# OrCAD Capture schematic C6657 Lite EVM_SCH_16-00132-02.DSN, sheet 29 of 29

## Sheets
29 PAGE22 : FPGA-POWER,RESET,McBSP: size C; title: FPGA-POWER,RESET,McBSP
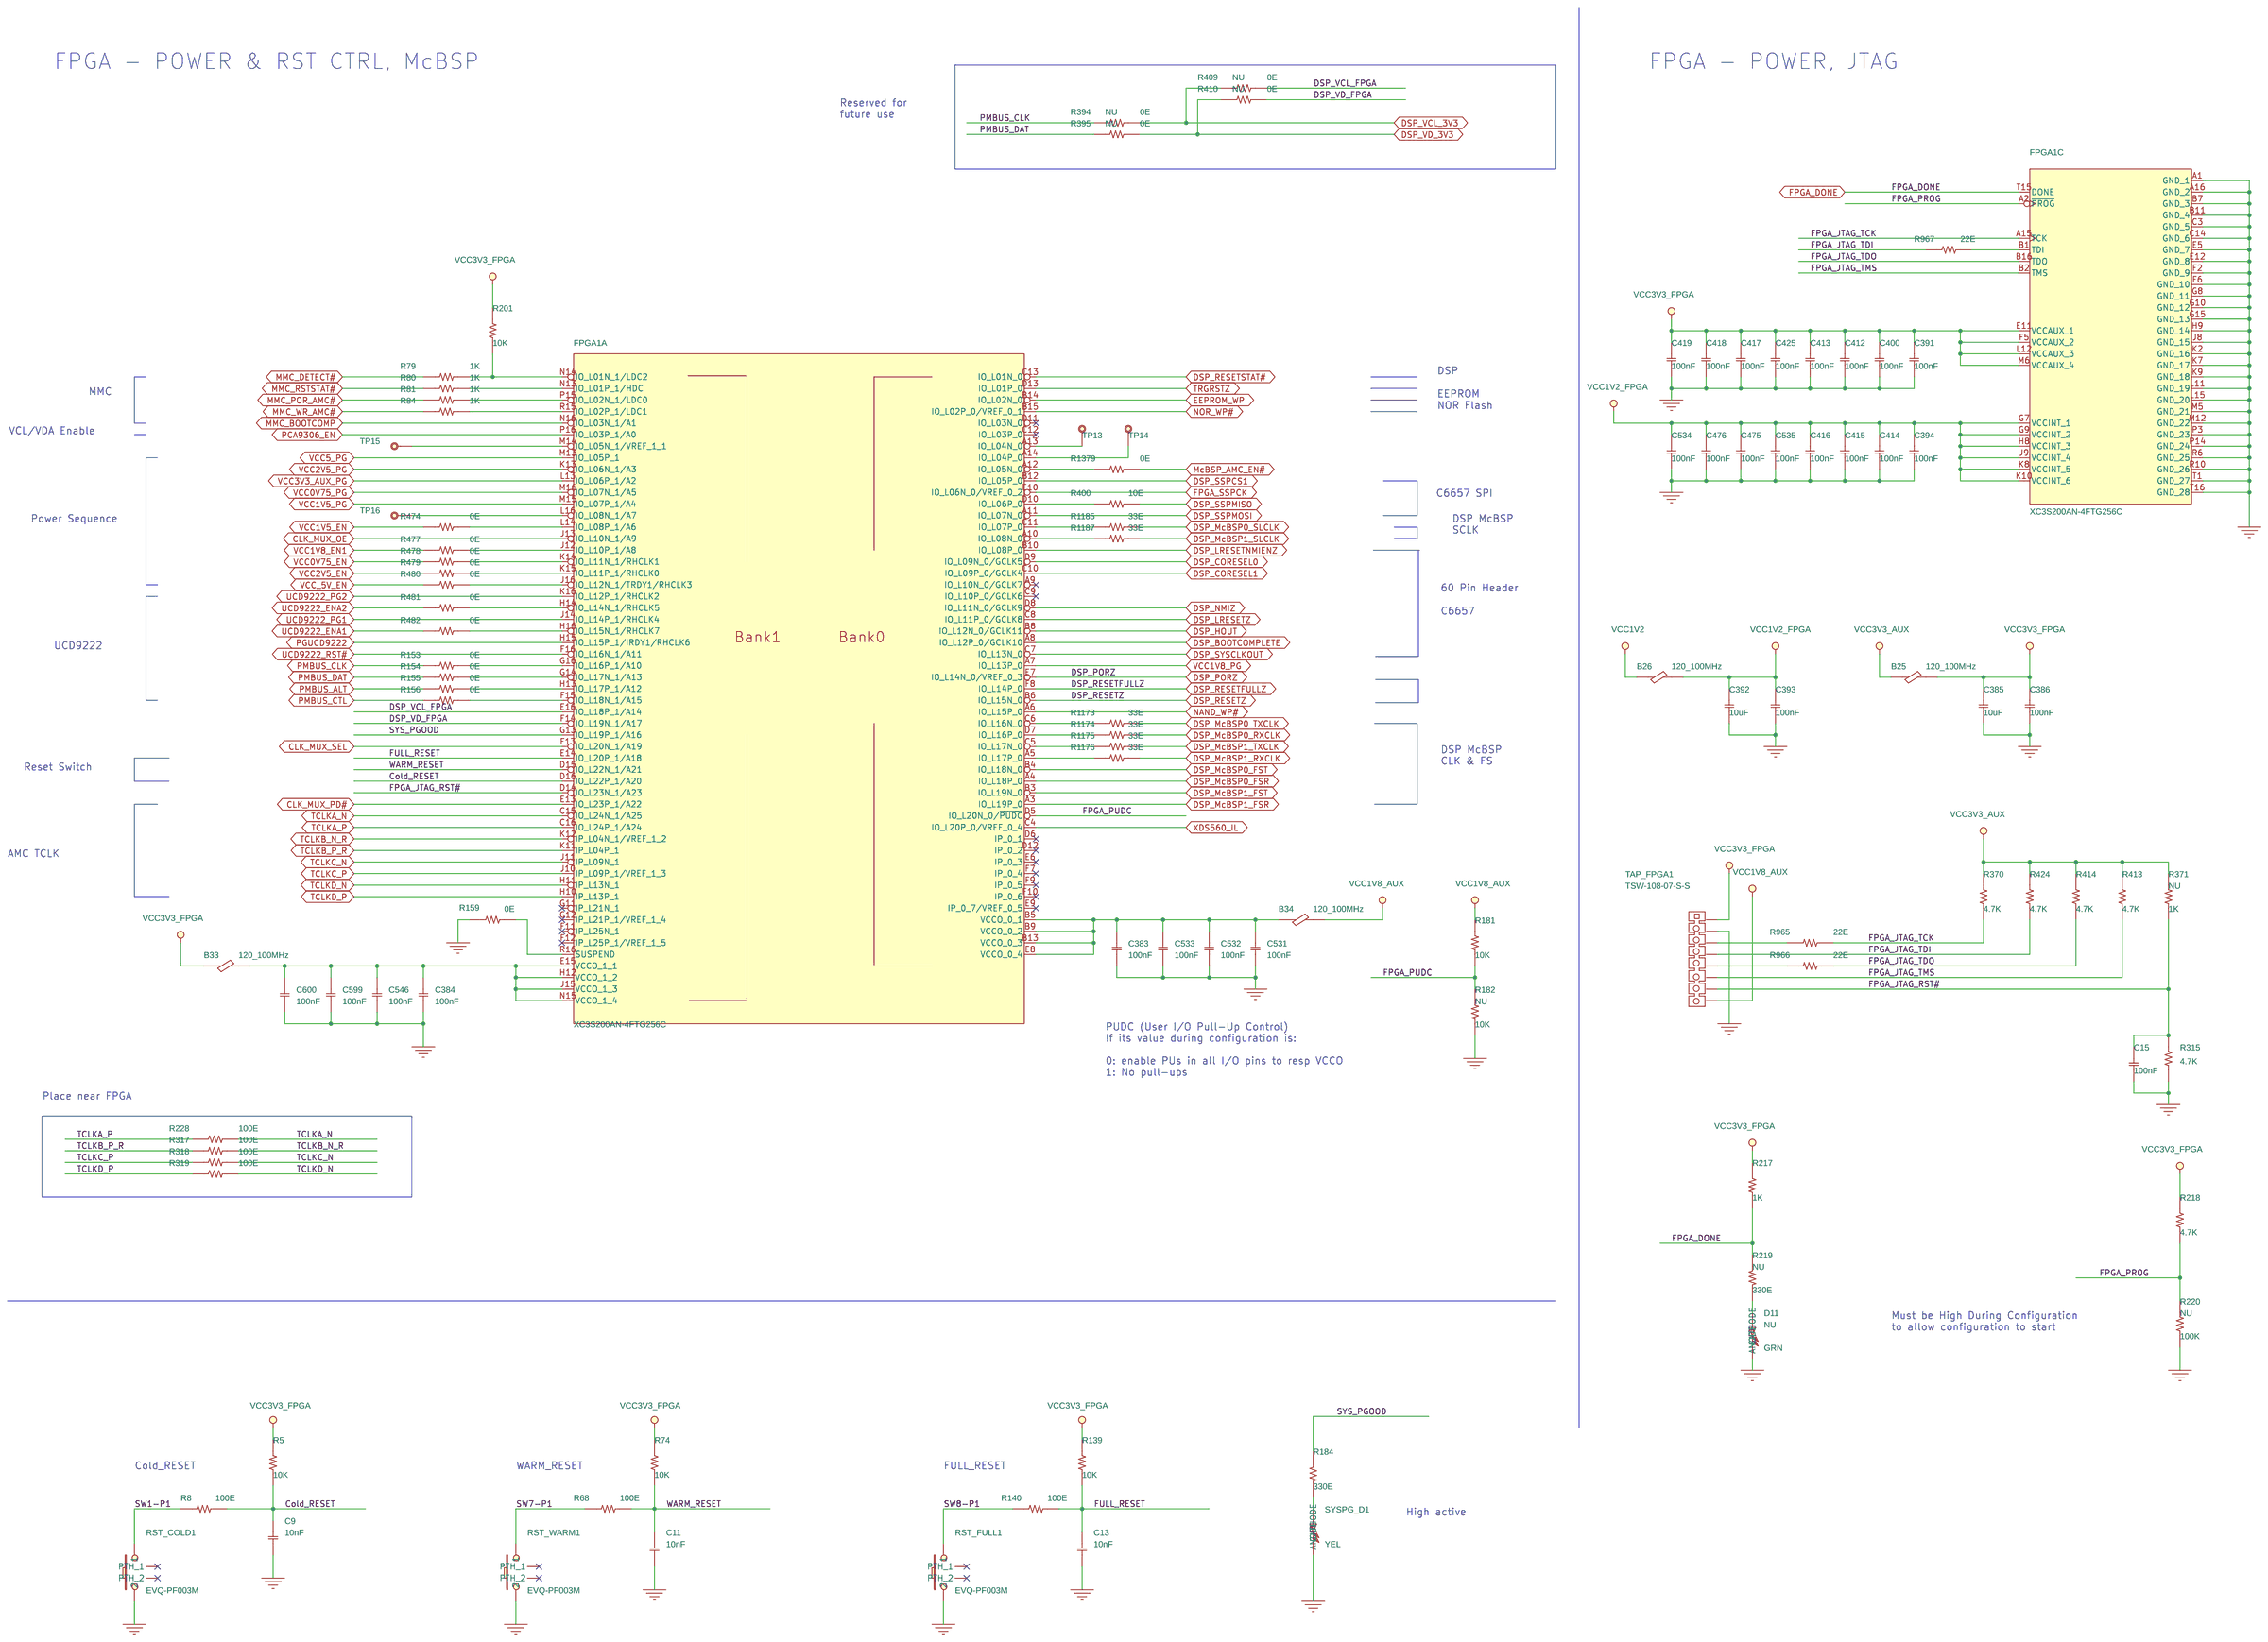
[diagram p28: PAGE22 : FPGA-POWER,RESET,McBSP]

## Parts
sheet PAGE22 : FPGA-POWER,RESET,McBSP
B25  120_100MHz  [L0603]
B26  120_100MHz  [L0603]
B33  120_100MHz  [L0603]
B34  120_100MHz  [L0603]
C9  10nF  [C0402]
C11  10nF  [C0402]
C13  10nF  [C0402]
C15  100nF  [C0402]
C383  100nF  [C0402]
C384  100nF  [C0402]
C385  10uF  [C0603]
C386  100nF  [C0402]
C391  100nF  [C0402]
C392  10uF  [C0603]
C393  100nF  [C0402]
C394  100nF  [C0402]
C400  100nF  [C0402]
C412  100nF  [C0402]
C413  100nF  [C0402]
C414  100nF  [C0402]
C415  100nF  [C0402]
C416  100nF  [C0402]
C417  100nF  [C0402]
C418  100nF  [C0402]
C419  100nF  [C0402]
C425  100nF  [C0402]
C475  100nF  [C0402]
C476  100nF  [C0402]
C531  100nF  [C0402]
C532  100nF  [C0402]
C533  100nF  [C0402]
C534  100nF  [C0402]
C535  100nF  [C0402]
C546  100nF  [C0402]
C599  100nF  [C0402]
C600  100nF  [C0402]
D11  GRN  [LED_0603]
R5  10K  [R0402]
R8  100E  [R0402]
R68  100E  [R0402]
R74  10K  [R0402]
R79  1K  [R0402]
R80  1K  [R0402]
R81  1K  [R0402]
R84  1K  [R0402]
R139  10K  [R0402]
R140  100E  [R0402]
R153  0E  [R0402]
R154  0E  [R0402]
R155  0E  [R0402]
R156  0E  [R0402]
R159  0E  [R0402]
R181  10K  [R0402]
R182  10K  [R0402]
R184  330E  [R0402]
R201  10K  [R0402]
R217  1K  [R0402]
R218  4.7K  [R0402]
R219  330E  [R0402]
R220  100K  [R0402]
R228  100E  [R0402]
R315  4.7K  [R0402]
R317  100E  [R0402]
R318  100E  [R0402]
R319  100E  [R0402]
R370  4.7K  [R0402]
R371  1K  [R0402]
R394  0E  [R0402]
R395  0E  [R0402]
R400  10E  [R0402]
R409  0E  [R0402]
R410  0E  [R0402]
R413  4.7K  [R0402]
R414  4.7K  [R0402]
R424  4.7K  [R0402]
R474  0E  [R0402]
R477  0E  [R0402]
R478  0E  [R0402]
R479  0E  [R0402]
R480  0E  [R0402]
R481  0E  [R0402]
R482  0E  [R0402]
R965  22E  [R0402]
R966  22E  [R0402]
R967  22E  [R0402]
R1173  33E  [R0402]
R1174  33E  [R0402]
R1175  33E  [R0402]
R1176  33E  [R0402]
R1185  33E  [R0402]
R1187  33E  [R0402]
R1379  0E  [R0402]
RST_COLD1  EVQ-PF003M  [SW_EVQ-PF003M]
RST_FULL1  EVQ-PF003M  [SW_EVQ-PF003M]
RST_WARM1  EVQ-PF003M  [SW_EVQ-PF003M]
SYSPG_D1  YEL  [LED_LTST-C171]
TAP_FPGA1  TSW-108-07-S-S  [HD_8x1P_100_D]
TP13  Test Point  [TP-S40]
TP14  Test Point  [TP-S40]
TP15  Test Point  [TP-S40]
TP16  Test Point  [TP-S40]
sheet PAGE23 : FPGA-BM & SMART REF
FPGA1  XC3S200AN-4FTG256C  [BGA_256P_39_669x669_H61]  (sections A,B,C)

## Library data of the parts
B25 B26 B33 B34 = 1212_BEAD_0: FERRITE CHIP 120 OHM 2000MA 0603; Manufacture Part Number: BLM18PG121SN1; Mfg: Murata; Mfg Part#: BLM18PG121SN1D; Oper. Temp. Range: -55C to 85C; Package: 0603; ProcessType: SMT; RoHS: Yes; Tolerance: 25%; Vendor: DigiKey; Vendor Part#: 490-1037-1-ND; eI Part#: 04_00023_01
C9 C11 C13 = 11_C_0: CAP 10nF 16V CERAMIC 0402 SMD; Alt Mfg: Murata; Alt Mfg Part#: GRM155R71C103KA01D; Manufacture Part Number: C1005X7R1C103K||2238 787 15636||CC0402KRX7R7BB103; Mfg: Panasonic - ECG; Mfg Part#: ECJ-0EB1C103K; Oper. Temp. Range: -55C to 125C; Package: 0402; ProcessType: SMT; RoHS: Yes; Tolerance: 10%; Vendor: DigiKey; Vendor Part#: PCC103BQCT-ND; eI Part#: 03_00025_01
C15 C383 C384 C386 C391 C393 C394 C400 C412-C419 C425 C475 C476 C531-C535 C546 C599 C600 = 11_C_0: CAP CER 0.1UF 10V 10% X5R 0402; Alt Mfg: Murata; Alt Mfg Part#: GRM155R61A104KA01D; Manufacture Part Number: 2238 787 15649||CC0402KRX7R7BB104; Mfg: Yageo; Mfg Part#: CC0402KRX5R6BB104; Oper. Temp. Range: -55C to 85C; Package: 0402; ProcessType: SMT; RoHS: Yes; Tolerance: 10%; Vendor: DigiKey; Vendor Part#: 311-1336-1-ND; eI Part#: 03_00021_02
C385 C392 = 11_C_0: CAP CER 10UF 6.3V 20% X5R 0603; Manufacture Part Number: C1608X5R0J106MT||2255 206 13776||CC0603MRX5R5BB106; Mfg: Murata; Mfg Part#: GRM188R60J106ME47D; Oper. Temp. Range: -55C to 85C; Package: 0603; ProcessType: SMT; RoHS: Yes; Tolerance: 20%; Vendor: DigiKey; Vendor Part#: 490-3896-1-ND; eI Part#: 03_00058_03
D11 = 130_LED_LED-0603_G_0: LED 565NM GRN DIFF 0603 SMD; Manufacture Part Number: KP-1608SGD; Mfg: Lumex Opto/Components Inc; Mfg Part#: SML-LX0603GW-TR; Mounting Status: NU; Package: 0603; ProcessType: SMT; RoHS: Yes; Vendor: DigiKey; Vendor Part#: 67-1549-1-ND; eI Part#: 06_00007_01
R5 R74 R139 R181 R201 = 10_R_0: RES 10.0K OHM 1/10W 1% 0402 SMD; Alt Mfg: Yageo; Alt Mfg Part#: RC0402FR-0710KL; Manufacture Part Number: 0402WGF1002TCE||RM04FTN1002; Mfg: Panasonic - ECG; Mfg Part#: ERJ-2RKF1002X; Oper. Temp. Range: -55C ~ 125C; Package: 0402; ProcessType: SMT; Remark: Alt part is 1/16W; RoHS: Yes; Tolerance: 1%; Vendor: DigiKey; Vendor Part#: P10.0KLCT-ND; eI Part#: 02_00027_01
R8 R68 R140 R228 R317-R319 = 10_R_0: RES 100 OHM 1/10W 1% 0402 SMD; Manufacture Part Number: 0402WGF1000TCE||232270671001L||RM04FTN1000; Mfg: Panasonic - ECG; Mfg Part#: ERJ-2RKF1000X; Oper. Temp. Range: -55C to 125C; Package: 0402; ProcessType: SMT; RoHS: Yes; Tolerance: 1%; Vendor: DigiKey; Vendor Part#: P100LCT-ND; eI Part#: 02_00043_02
R79-R81 R84 R217 = 10_R_0: RES 1.00K OHM 1/10W 1% 0402 SMD; Alt Mfg: Yageo; Alt Mfg Part#: RC0402FR-071KL; MOUNTED: <MOUNTED>; Manufacture Part Number: 0402WGF1001TCE||RM04FTN1001; Mfg: Panasonic - ECG; Mfg Part#: ERJ-2RKF1001X; Oper. Temp. Range: -55C to 125C; Package: 0402; ProcessType: SMT; RoHS: Yes; Tolerance: 1%; Vendor: DigiKey; Vendor Part#: P1.00KLCT-ND; eI Part#: 02_00045_01
R153-R156 R159 R474 R477-R482 R1379 = 10_R_0: RES ZERO OHM 1/10W 5% 0402 SMD; Alt Mfg: Yageo; Alt Mfg Part#: RC0402JR-070RL; Mfg: Panasonic - ECG; Mfg Part#: ERJ-2GE0R00X; Oper. Temp. Range: -55C to 125C; Package: 0402; ProcessType: SMT; Remark: Alt part is 1/16W; RoHS: Yes; Tolerance: 5%; Vendor: DigiKey; Vendor Part#: P0.0JCT-ND; eI Part#: 02_00019_01
R182 = 10_R_0: RES 10.0K OHM 1/10W 1% 0402 SMD; Alt Mfg: Yageo; Alt Mfg Part#: RC0402FR-0710KL; Manufacture Part Number: 0402WGF1002TCE||RM04FTN1002; Mfg: Panasonic - ECG; Mfg Part#: ERJ-2RKF1002X; Mounting Status: NU; Mounting_Status: NU; Oper. Temp. Range: -55C ~ 125C; Package: 0402; ProcessType: SMT; Remark: Alt part is 1/16W; RoHS: Yes; Tolerance: 1%; Vendor: DigiKey; Vendor Part#: P10.0KLCT-ND; eI Part#: 02_00027_01
R184 = 10_R_0: RES 330 OHM 1/10W 5% 0402 SMD; Alt Mfg: Yageo; Alt Mfg Part#: RC0402JR-07330RL; Manufacture Part Number: 0402WGJ0331TCE||RM04JTN331; Mfg: Panasonic - ECG; Mfg Part#: ERJ-2GEJ331X; Package: 0402; ProcessType: SMT; Remark: Alt part is 1/16W; RoHS: Yes; Tolerance: 5%; Vendor: DigiKey; Vendor Part#: P330JCT-ND; eI Part#: 02_00032_01
R218 = 10_R_0: RES 4.7K OHM 1/10W 5% 0402 SMD; Alt Mfg: Yageo; Alt Mfg Part#: RC0402JR-074K7L; Manufacture Part Number: 0402WGJ0472TCE||RC0402JR-074K7L||RM04JTN472; Mfg: Panasonic - ECG; Mfg Part#: ERJ-2GEJ472X; Oper. Temp. Range: -55C to 125C; Package: 0402; ProcessType: SMT; Remark: Alt part is 1/16W; RoHS: Yes; Tolerance: 5%; Vendor: DigiKey; Vendor Part#: P4.7KJCT-ND; eI Part#: 02_00023_01
R219 = 10_R_0: RES 330 OHM 1/10W 5% 0402 SMD; Alt Mfg: Yageo; Alt Mfg Part#: RC0402JR-07330RL; Manufacture Part Number: 0402WGJ0331TCE||RM04JTN331; Mfg: Panasonic - ECG; Mfg Part#: ERJ-2GEJ331X; Mounting Status: NU; Mounting_Status: NU; Package: 0402; ProcessType: SMT; Remark: Alt part is 1/16W; RoHS: Yes; Tolerance: 5%; Vendor: DigiKey; Vendor Part#: P330JCT-ND; eI Part#: 02_00032_01
R220 = 10_R_0: RES 100K OHM 1/10W 1% 0402 SMD; Alt Mfg: Yageo; Alt Mfg Part#: RC0402FR-07100KL; Manufacture Part Number: 0402WGF1003TCE||RM04FTN1003; Mfg: Panasonic - ECG; Mfg Part#: ERJ-2RKF1003X; Mounting Status: NU; Mounting_Status: NU; Oper. Temp. Range: ±100ppm/°C; Package: 0402; ProcessType: SMT; RoHS: Yes; Tolerance: 1%; Vendor: DigiKey; Vendor Part#: P100KLCT-ND; eI Part#: 02_00262_01
R315 R370 R413 R414 R424 = 10_R_0: RES 4.7K OHM 1/10W 5% 0402 SMD; Alt Mfg: Yageo; Alt Mfg Part#: RC0402JR-074K7L; MOUNTED: <MOUNTED>; Manufacture Part Number: 0402WGJ0472TCE||RC0402JR-074K7L||RM04JTN472; Mfg: Panasonic - ECG; Mfg Part#: ERJ-2GEJ472X; Oper. Temp. Range: -55C to 125C; Package: 0402; ProcessType: SMT; Remark: Alt part is 1/16W; RoHS: Yes; Tolerance: 5%; Vendor: DigiKey; Vendor Part#: P4.7KJCT-ND; eI Part#: 02_00023_01
R371 = 10_R_0: RES 1.00K OHM 1/10W 1% 0402 SMD; Alt Mfg: Yageo; Alt Mfg Part#: RC0402FR-071KL; Manufacture Part Number: 0402WGF1001TCE||RM04FTN1001; Mfg: Panasonic - ECG; Mfg Part#: ERJ-2RKF1001X; Mounting Status: NU; Mounting_Status: NU; Oper. Temp. Range: -55C to 125C; Package: 0402; ProcessType: SMT; RoHS: Yes; Tolerance: 1%; Vendor: DigiKey; Vendor Part#: P1.00KLCT-ND; eI Part#: 02_00045_01
R394 R395 R409 R410 = 10_R_0: RES ZERO OHM 1/10W 5% 0402 SMD; Alt Mfg: Yageo; Alt Mfg Part#: RC0402JR-070RL; Mfg: Panasonic - ECG; Mfg Part#: ERJ-2GE0R00X; Mounting Status: NU; Mounting_Status: NU; Oper. Temp. Range: -55C to 125C; Package: 0402; ProcessType: SMT; Remark: Alt part is 1/16W; RoHS: Yes; Tolerance: 5%; Vendor: DigiKey; Vendor Part#: P0.0JCT-ND; eI Part#: 02_00019_01
R400 = 10_R_0: RES 10.0 OHM 1/10W 1% 0402 SMD; Manufacture Part Number: 0402WGJ0100TCE||RC0402JR-0710RL||RM04JTN100; Mfg: Panasonic - ECG; Mfg Part#: ERJ-2RKF10R0X; Oper. Temp. Range: -55C to 125C; Package: 0402; ProcessType: SMT; RoHS: Yes; Tolerance: 1%; Vendor: DigiKey; Vendor Part#: P10.0LCT-ND; eI Part#: 02_00060_01
R965-R967 = 10_R_0: RES 22 OHM 1/10W 5% 0402 SMD; Mfg: Panasonic - ECG; Mfg Part#: ERJ-2GEJ220X; Oper. Temp. Range: -55C to 125C; Package: 0402; ProcessType: SMT; Remark: Alt part is 1/16W; RoHS: Yes; Tolerance: 5%; Vendor: DigiKey; Vendor Part#: P22JCT-ND; eI Part#: 02_00233_01
R1173-R1176 R1185 R1187 = 10_R_0: RES 33.0 OHM 1/10W 1% 0402 SMD; Alt Mfg: Yageo; Alt Mfg Part#: RC0402FR-0733RL; Manufacture Part Number: 0402WGJ0330TCE||232270570339L||RC0402JR-0733RL||RM04JTN330; Mfg: Panasonic - ECG; Mfg Part#: ERJ-2RKF33R0X; Oper. Temp. Range: -55C to 125C; Package: 0402; ProcessType: SMT; Remark: Alt part is 1/16W; RoHS: Yes; Tolerance: 1%; Vendor: DigiKey; Vendor Part#: P33.0LCT-ND; eI Part#: 02_00018_05
RST_COLD1 RST_FULL1 RST_WARM1 = 160_SW-HDK632: SWITCH TACTILE SPST-NO 0.02A 15V; Manufacture Part Number: HDK632AR-ST; Mfg: Panasonic - ECG; Package: SW2PDIP; ProcessType: DIP; RoHS: Yes; Vendor: DigiKey; Vendor Part#: P10877S-ND; eI Part#: 11_00020_01
SYSPG_D1 = 130_LED_2P_B_0: LED AMBER YEL CLR THIN 0805 SMD; Alt Mfg: Lite-On Inc; Alt Mfg Part#: LTST-C170KSKT; Mfg: Lite-On Inc; Mfg Part#: LTST-C171KYKT; Package: 0805; ProcessType: SMT; RoHS: Yes; Vendor: DigiKey; Vendor Part#: 160-1429-1-ND; eI Part#: 06_00087_01
TAP_FPGA1 = 1653_JH8X1V_0: CONN HEADER 8POS .100" SGL GOLD; Manufacture Part Number: YP91-01104-08B1||21N12564-08S10B-01G-6/3; Mfg: Samtec; Package: PH8x1P-2.54; ProcessType: DIP; RoHS: Yes; Vendor: DigiKey; Vendor Part#: SAM1033-08-ND; eI Part#: 09_00660_01
TP13-TP16 = 00_TP-S40_0: TEST PAD TP-S40; Mfg: --NA--; Mfg Part#: --NA--; Oper. Temp. Range: --NA--; Package: --NA--; ProcessType: SMT; RoHS: Yes; Vendor: --NA--; Vendor Part#: --NA--; eI Part#: --NA--
FPGA1 = XC3S200AN-4FTG256C: IC SPARTAN-3AN FPGA 200K 256FTBG; Mfg: Xilinx Inc; Oper. Temp. Range: 0°C ~ 85°C; Package: FTBGA256; ProcessType: SMT; RoHS: Yes; Vendor: DigiKey; Vendor Part#: 122-1553-ND; eI Part#: 01_00848_01

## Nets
GND: C9.2 C11.2 C13.2 C15.2 C383.1 C384.1 C385.2 C386.1 C391.1 C392.2 C393.1 C394.1 C400.1 C412.1 C413.1 C414.1 C415.1 C416.1 C417.1 C418.1 C419.1 C425.1 C475.1 C476.1 C531.1 C532.1 C533.1 C534.1 C535.1 C546.1 C599.1 C600.1 D11.2(CATHODE) FPGA1.A1(GND_1) FPGA1.A16(GND_2) FPGA1.B7(GND_3) FPGA1.B11(GND_4) FPGA1.C3(GND_5) FPGA1.C14(GND_6) FPGA1.E5(GND_7) FPGA1.E12(GND_8) FPGA1.F2(GND_9) FPGA1.F6(GND_10) FPGA1.G8(GND_11) FPGA1.G10(GND_12) FPGA1.G15(GND_13) FPGA1.H9(GND_14) FPGA1.J8(GND_15) FPGA1.K2(GND_16) FPGA1.K7(GND_17) FPGA1.K9(GND_18) FPGA1.L11(GND_19) FPGA1.L15(GND_20) FPGA1.M5(GND_21) FPGA1.M12(GND_22) FPGA1.P3(GND_23) FPGA1.P14(GND_24) FPGA1.R6(GND_25) FPGA1.R10(GND_26) FPGA1.T1(GND_27) FPGA1.T16(GND_28) R159.1 R182.1 R220.1 R315.2 RST_COLD1.B(2) RST_FULL1.B(2) RST_WARM1.B(2) SYSPG_D1.2(CATHODE) TAP_FPGA1.2 ; also on sheet 4 5 6 7 8 9 12 13 14 15 16 19 20 23 26 27 28
VCC0V75_EN: R478.1 ; also on sheet 15
VCC0V75_PG: FPGA1.M16(IO_L07N_1/A5) ; also on sheet 15
VCC1V2: B26.1 ; also on sheet 15 19
VCC1V2_FPGA: B26.2 C392.1 C393.2 C394.2 C414.2 C415.2 C416.2 C475.2 C476.2 C534.2 C535.2 FPGA1.G7(VCCINT_1) FPGA1.G9(VCCINT_2) FPGA1.H8(VCCINT_3) FPGA1.J9(VCCINT_4) FPGA1.K8(VCCINT_5) FPGA1.K10(VCCINT_6)
VCC1V5_EN: R474.1 ; also on sheet 14
VCC1V5_PG: FPGA1.M15(IO_L07P_1/A4) ; also on sheet 14
VCC1V8_AUX: B34.2 R181.2 TAP_FPGA1.8 ; also on sheet 6 12 15 26
VCC1V8_EN1: R477.1 ; also on sheet 15
VCC1V8_PG: FPGA1.A7(IO_L13P_0) ; also on sheet 15 28
VCC2V5_EN: R479.1 ; also on sheet 15
VCC2V5_PG: FPGA1.K13(IO_L06N_1/A3) ; also on sheet 15
VCC3V3_AUX: B25.1 R370.2 R371.2 R413.2 R414.2 R424.2 ; also on sheet 4 6 12 13 14 15 16 20 23 26 27 28
VCC3V3_AUX_PG: FPGA1.L13(IO_L06P_1/A2) ; also on sheet 14
VCC3V3_FPGA: B25.2 B33.1 C385.1 C386.2 C391.2 C400.2 C412.2 C413.2 C417.2 C418.2 C419.2 C425.2 FPGA1.E11(VCCAUX_1) FPGA1.F5(VCCAUX_2) FPGA1.L12(VCCAUX_3) FPGA1.M6(VCCAUX_4) R5.1 R74.1 R139.1 R201.1 R217.2 R218.2 TAP_FPGA1.1 ; also on sheet 26
VCC5_PG: FPGA1.M13(IO_L05P_1) ; also on sheet 14
VCC_5V_EN: R480.1 ; also on sheet 14
CLK_MUX_OE: FPGA1.J13(IO_L10N_1/A9) ; also on sheet 28
CLK_MUX_PD#: FPGA1.E13(IO_L23P_1/A22) ; also on sheet 28
CLK_MUX_SEL: FPGA1.F13(IO_L20N_1/A19) ; also on sheet 28
Cold_RESET: C9.1 FPGA1.D16(IO_L22P_1/A20) R5.2 R8.2
DSP_BOOTCOMPLETE: FPGA1.A8(IO_L12P_0/GCLK10) ; also on sheet 4
DSP_CORESEL0: FPGA1.D9(IO_L09N_0/GCLK5) ; also on sheet 4
DSP_CORESEL1: FPGA1.C10(IO_L09P_0/GCLK4) ; also on sheet 4
DSP_HOUT: FPGA1.B8(IO_L12N_0/GCLK11) ; also on sheet 4
DSP_LRESETNMIENZ: FPGA1.B10(IO_L08P_0) ; also on sheet 4
DSP_LRESETZ: FPGA1.C8(IO_L11P_0/GCLK8) ; also on sheet 4
DSP_McBSP0_FSR: FPGA1.A4(IO_L18P_0) ; also on sheet 13 23
DSP_McBSP0_FST: FPGA1.B4(IO_L18N_0) ; also on sheet 13 23
DSP_McBSP0_RXCLK: R1174.2 ; also on sheet 13 23
DSP_McBSP0_SLCLK: R1185.2 ; also on sheet 13 23
DSP_McBSP0_TXCLK: R1173.2 ; also on sheet 13 23
DSP_McBSP1_FSR: FPGA1.A3(IO_L19P_0) ; also on sheet 13 23
DSP_McBSP1_FST: FPGA1.B3(IO_L19N_0) ; also on sheet 13 23
DSP_McBSP1_RXCLK: R1176.2 ; also on sheet 13 23
DSP_McBSP1_SLCLK: R1187.2 ; also on sheet 13 23
DSP_McBSP1_TXCLK: R1175.2 ; also on sheet 13 23
DSP_NMIZ: FPGA1.D8(IO_L11N_0/GCLK9) ; also on sheet 4
DSP_PORZ: FPGA1.E7(IO_L14N_0/VREF_0_3) ; also on sheet 4
DSP_RESETFULLZ: FPGA1.F8(IO_L14P_0) ; also on sheet 4
DSP_RESETSTAT#: FPGA1.C13(IO_L01N_0) ; also on sheet 4
DSP_RESETZ: FPGA1.B6(IO_L15N_0) ; also on sheet 4
DSP_SSPCS1: FPGA1.B12(IO_L05P_0) ; also on sheet 4 23
DSP_SSPMISO: R400.2 ; also on sheet 4 23
DSP_SSPMOSI: FPGA1.A11(IO_L07N_0) ; also on sheet 4 23
DSP_SYSCLKOUT: FPGA1.C7(IO_L13N_0) ; also on sheet 28
DSP_VCL_3V3: R394.2 R409.1 ; also on sheet 28
DSP_VCL_FPGA: FPGA1.E16(IO_L18P_1/A14) R409.2
DSP_VD_3V3: R395.2 R410.1 ; also on sheet 28
DSP_VD_FPGA: FPGA1.F14(IO_L19N_1/A17) R410.2
EEPROM_WP: FPGA1.B14(IO_L02N_0) ; also on sheet 4
FPGA_DONE: FPGA1.T15(DONE) R217.1 R219.2 ; also on sheet 26
FPGA_JTAG_RST#: C15.1 FPGA1.D14(IO_L23N_1/A23) R315.1 R371.1 TAP_FPGA1.7
FPGA_JTAG_TCK: FPGA1.A15(TCK) R370.1 R965.1
FPGA_JTAG_TDI: R424.1 R967.2 TAP_FPGA1.4
FPGA_JTAG_TDO: FPGA1.B16(TDO) R414.1 R966.1
FPGA_JTAG_TMS: FPGA1.B2(TMS) R413.1 TAP_FPGA1.6
FPGA_PROG: FPGA1.A2(~{PROG}) R218.1 R220.2
FPGA_PUDC: FPGA1.D5(IO_L20N_0/~{PUDC}) R181.1 R182.2
FPGA_SSPCK: FPGA1.E10(IO_L06N_0/VREF_0_2) ; also on sheet 4
FULL_RESET: C13.1 FPGA1.E14(IO_L20P_1/A18) R139.2 R140.2
McBSP_AMC_EN#: R1379.2 ; also on sheet 12
MMC_BOOTCOMP: FPGA1.N16(IO_L03N_1/A1) ; also on sheet 23
MMC_DETECT#: R79.1 ; also on sheet 23
MMC_POR_AMC#: R81.1 ; also on sheet 23
MMC_RSTSTAT#: R80.1 ; also on sheet 23
MMC_WR_AMC#: R84.1 ; also on sheet 23
NAND_WP#: FPGA1.A6(IO_L15P_0) ; also on sheet 16
NOR_WP#: FPGA1.B15(IO_L02P_0/VREF_0_1) ; also on sheet 4
PCA9306_EN: FPGA1.P16(IO_L03P_1/A0) ; also on sheet 28
PGUCD9222: FPGA1.H15(IO_L15P_1/IRDY1/RHCLK6) ; also on sheet 27
PMBUS_ALT: R155.1 ; also on sheet 27
PMBUS_CLK: R153.1 R394.1 ; also on sheet 27
PMBUS_CTL: R156.1 ; also on sheet 27
PMBUS_DAT: R154.1 R395.1 ; also on sheet 27
SW1-P1: R8.1 RST_COLD1.A(1)
SW7-P1: R68.1 RST_WARM1.A(1)
SW8-P1: R140.1 RST_FULL1.A(1)
SYS_PGOOD: FPGA1.G13(IO_L19P_1/A16) R184.2
TCLKA_N: FPGA1.C15(IO_L24N_1/A25) R228.1 ; also on sheet 12
TCLKA_P: FPGA1.C16(IO_L24P_1/A24) R228.2 ; also on sheet 12
TCLKB_N_R: FPGA1.K12(IP_L04N_1/VREF_1_2) R317.1 ; also on sheet 20
TCLKB_P_R: FPGA1.K11(IP_L04P_1) R317.2 ; also on sheet 20
TCLKC_N: FPGA1.J11(IP_L09N_1) R318.1 ; also on sheet 12
TCLKC_P: FPGA1.J10(IP_L09P_1/VREF_1_3) R318.2 ; also on sheet 12
TCLKD_N: FPGA1.H11(IP_L13N_1) R319.1 ; also on sheet 12
TCLKD_P: FPGA1.H10(IP_L13P_1) R319.2 ; also on sheet 12
TRGRSTZ: FPGA1.D13(IO_L01P_0) ; also on sheet 16
UCD9222_ENA1: R482.1 ; also on sheet 27
UCD9222_ENA2: R481.1 ; also on sheet 27
UCD9222_PG1: FPGA1.J14(IO_L14P_1/RHCLK4) ; also on sheet 27
UCD9222_PG2: FPGA1.K16(IO_L12P_1/RHCLK2) ; also on sheet 27
UCD9222_RST#: FPGA1.F16(IO_L16N_1/A11) ; also on sheet 27
WARM_RESET: C11.1 FPGA1.D15(IO_L22N_1/A21) R68.2 R74.2
XDS560_IL: FPGA1.C4(IO_L20P_0/VREF_0_4) ; also on sheet 14
N34083796: B34.1 C383.2 C531.2 C532.2 C533.2 FPGA1.B5(VCCO_0_1) FPGA1.B9(VCCO_0_2) FPGA1.B13(VCCO_0_3) FPGA1.E8(VCCO_0_4)
N34084022: B33.2 C384.2 C546.2 C599.2 C600.2 FPGA1.E15(VCCO_1_1) FPGA1.H12(VCCO_1_2) FPGA1.J15(VCCO_1_3) FPGA1.N15(VCCO_1_4)
N34085139: R184.1 SYSPG_D1.1(ANODE)
N45902128: FPGA1.P15(IO_L02N_1/LDC0) R81.2
N46486429: FPGA1.R15(IO_L02P_1/LDC1) R84.2
N48846851: FPGA1.R16(SUSPEND) R159.2
N49678460: FPGA1.D10(IO_L06P_0) R400.1
N58588168: FPGA1.N13(IO_L01P_1/HDC) R80.2
N58588223: FPGA1.N14(IO_L01N_1/LDC2) R79.2 R201.2
N59455279: FPGA1.G16(IO_L16P_1/A10) R153.2
N59455282: FPGA1.G14(IO_L17N_1/A13) R154.2
N59455285: FPGA1.H13(IO_L17P_1/A12) R155.2
N59455293: FPGA1.F15(IO_L18N_1/A15) R156.2
N64258678: FPGA1.A13(IO_L04N_0) TP13.1
N64258680: FPGA1.A14(IO_L04P_0) TP14.1
N64262461: FPGA1.L16(IO_L08N_1/A7) TP16.1
N65632400: FPGA1.L14(IO_L08P_1/A6) R474.2
N65632443: FPGA1.J12(IO_L10P_1/A8) R477.2
N65632446: FPGA1.K14(IO_L11N_1/RHCLK1) R478.2
N65632449: FPGA1.K15(IO_L11P_1/RHCLK0) R479.2
N65632452: FPGA1.J16(IO_L12N_1/TRDY1/RHCLK3) R480.2
N65632526: FPGA1.H14(IO_L14N_1/RHCLK5) R481.2
N65632529: FPGA1.H16(IO_L15N_1/RHCLK7) R482.2
N65693492: FPGA1.M14(IO_L05N_1/VREF_1_1) TP15.1
N70665808: FPGA1.B1(TDI) R967.1
N70747877: D11.1(ANODE) R219.1
N71226418: R966.2 TAP_FPGA1.5
N71226439: R965.2 TAP_FPGA1.3
N75632454: FPGA1.A12(IO_L05N_0) R1379.1
N75665004: FPGA1.D7(IO_L16P_0) R1174.1
N75665006: FPGA1.A5(IO_L17P_0) R1176.1
N75665012: FPGA1.C5(IO_L17N_0) R1175.1
N75665014: FPGA1.C6(IO_L16N_0) R1173.1
N75674847: FPGA1.A10(IO_L08N_0) R1187.1
N75674849: FPGA1.C11(IO_L07P_0) R1185.1

Not connected (* = marked no-connect by the designer): FPGA1 A9(IO_L10N_0/GCLK7)* C9(IO_L10P_0/GCLK6)* C12(IO_L03P_0)* D6(IP_0_1)* D11(IO_L03N_0)* D12(IP_0_2)* E6(IP_0_3)* E9(IP_0_7/VREF_0_5)* F7(IP_0_4)* F9(IP_0_5)* F10(IP_0_6)* F11(IP_L25N_1)* F12(IP_L25P_1/VREF_1_5)* G11(IP_L21N_1)* G12(IP_L21P_1/VREF_1_4)*; RST_COLD1 G1(PTH_1)* G2(PTH_2)*; RST_FULL1 G1(PTH_1)* G2(PTH_2)*; RST_WARM1 G1(PTH_1)* G2(PTH_2)*

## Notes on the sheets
sheet 29
- FPGA - POWER & RST CTRL, McBSP
- FPGA - POWER, JTAG
- Reserved for
  future use
- DSP
- MMC
- EEPROM
- NOR Flash
- VCL/VDA Enable
- C6657 SPI
- Power Sequence
- DSP McBSP
  SCLK
- 60 Pin Header
- C6657
- UCD9222
- DSP McBSP
  CLK & FS
- Reset Switch
- AMC TCLK
- PUDC (User I/O Pull-Up Control)
  If its value during configuration is:
  0: enable PUs in all I/O pins to resp VCCO
  1: No pull-ups
- Place near FPGA
- Must be High During Configuration
  to allow configuration to start
- Cold_RESET
- WARM_RESET
- FULL_RESET
- High active
